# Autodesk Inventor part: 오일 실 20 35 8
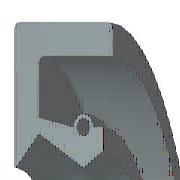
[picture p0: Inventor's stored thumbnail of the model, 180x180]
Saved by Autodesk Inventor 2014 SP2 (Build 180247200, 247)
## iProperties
IsCustomPart: 0
Created: 2018-09
Part Number: 오일 실 20 35 8
Material: 고무
Description: 오일-실
Document SubType Name: Modeling
Standard: KS B 2804
Standards Organization: KS
Language: ko-KR
Size Designation: D - 20 35 8
Categories: <MemberInstance><Categories><Category DisplayName="샤프트 부품" InternalName="7f7aeb1f-a693-4053-b835-cee3144e0d98" Mnemonic="SHFT"><Category DisplayName="실링" Intern
Density: 0.93 g/cm^3
Mass: 2.54606 g
Surface Area: 35.9421 cm^2
Volume: 2.7377 cm^3
Appearance: 보라색
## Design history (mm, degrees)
revolve "본체" stored, may be unused: angle "d17" = 90 deg
revolve "스프링1" stored, may be unused: angle "d18" = 90 deg
body "Solid1"
sketch "스케치1"
  geometry: L1 (0, 17.5)-(8, 17.5); L2 (8, 15.75)-(1.75, 15.75); L3 (1.75, 11.75)-(4.9, 10); L4 (4.9, 10)-(0, 10); L5 (0, 0)-(9.586, 0) reference; L6 (4.9, 10)-(6.3, 10.875); L7 (0, 18)-(0, -3) reference; L8 (-1.941, 0)-(11.507, 0) reference; L9 (4.2, 12.1)-(1.75, 12.71); L10 (1.75, 12.71)-(1.75, 15.75); L11 (0, 17.5)-(0, 10.088); L12 (4.9, 10)-(0, 10); L13 (1.75, 11.75)-(0.152, 10.028); L14 (8, 17.5)-(8, 15.75); L15 (5.6, 12.1)-(6.3, 12.1); L16 (6.3, 12.1)-(6.3, 10.875); C1 r 0.455 at (4.9, 12.1); A1 r 0.7 centre (4.9, 12.1) between (5.6, 12.1) and (4.2, 12.1); A2 r 0.088 centre (0.088, 10.088) between (0, 10.088) and (0.152, 10.028); 1 further point
  constraints: 28 end point, 5 horizontal alignment, 5 point on line, 4 point on circle, 4 vertical alignment, 3 centre point, 3 tangent, 2 collinear, 2 horizontal, 2 perpendicular, 1 coincident, 1 parallel
  dimensions: "d0" = 35 diameter of L1 L5 (= SD2); "d1" = 1.75 distance of L1.end L2.start (= SD); "d2" = 0.91 diameter of C1 (= SPDI); "d3" = 1.4 diameter of A1 (= SPDA); "d4" = 20 diameter of L3.end L5 (= NND); "d5" = 23.5 diameter of L3.start L5 (= TKDM); "d7" = 25.42 diameter of L9.end L5 (= TKDM + 0.24 x SWDT); "d8" = 1.75 distance between parallel lines of L11 L10 (= SD); "d9" = 4.9 distance from line of L11 C1.centre (= SPDST); "d10" = 24.2 diameter of C1.centre L5 (= HLDM); "d11" = 0.0875 radius of A2 (= 0.25 x LAB); "d12" = 6.3 distance between parallel lines of L11 L16 (= SDI); "d13" = 21.75 diameter of L6.end L5 (= ABDM); "d14" = 8 distance from line of L11 L1.end (= SWDT)
fillet "모깎기1" dims "d6" = 0.3 (= RR)
other parameters: "SD2" = 35 [user parameter; used in 1 equation term], "SWDT" = 8 [user parameter; used in 2 equation terms], "RR" = 0.3 [user parameter; used in 1 equation term], "SD" = 1.75 [user parameter; used in 2 equation terms], "NND" = 20 [user parameter; used in 1 equation term], "SPDA" = 1.4 [user parameter; used in 1 equation term], "SPDI" = 0.91 [user parameter; used in 1 equation term], "TKDM" = 23.5 [user parameter; used in 2 equation terms], "HLDM" = 24.2 [user parameter; used in 1 equation term], "ABDM" = 21.75 [user parameter; used in 1 equation term], "SDI" = 6.3 [user parameter; used in 1 equation term], "SPDST" = 4.9 [user parameter; used in 1 equation term], "LAB" = 0.35 [user parameter; used in 1 equation term], "d15" = 0, "d16" = 0, "d19" = 0
